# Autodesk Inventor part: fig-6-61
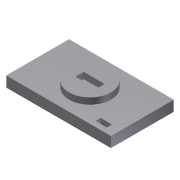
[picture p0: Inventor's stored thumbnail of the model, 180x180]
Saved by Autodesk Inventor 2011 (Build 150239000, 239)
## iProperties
Created: 2007-01
Part Number: fig-6-61
Document SubType Name: Modeling
Designer: Administrator
Density: 1 g/cm^3
Author: Administrator
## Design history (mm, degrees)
sketch "Sketch1"
  geometry: L1 (-50, 30)-(50, 30); L2 (50, 30)-(50, -30); L3 (50, -30)-(-50, -30); L4 (-50, -30)-(-50, 30); 1 further point
  constraints: 8 end point, 2 parallel, 1 horizontal, 1 perpendicular, 1 other
  dimensions: "d0" = 50 distance from line of L4 point (0, 0); "d1" = 100 distance of L1.start L1.end; "d2" = 30 distance from line of L3 point (0, 0); "d3" = 60 distance between parallel lines of L3 L1
extrude "Extrusion1" new body sketch "Sketch1" distance "d4" = 10; taper "d5" = 0 deg
sketch "Sketch2"
  geometry: L1 (10, -4)-(-10, -4); L2 (-10, -4)-(-10, 4); L3 (-10, 4)-(10, 4); L4 (10, 4)-(10, -4); C1 r 20 at (0, 0); 1 further point
  constraints: 8 end point, 2 parallel, 1 centre point, 1 coincident, 1 horizontal, 1 perpendicular, 1 other
  dimensions: "d6" = 40 diameter of C1; "d7" = 4 distance from line of L3 point (0, 0); "d8" = 8 distance between parallel lines of L1 L3; "d9" = 10 distance from line of L2 point (0, 0); "d10" = 20 distance between parallel lines of L4 L2
extrude "Extrusion2" join sketch "Sketch2" distance "d11" = 6; taper "d12" = 0 deg
sketch "Sketch3"
  geometry: L1 (30, -20)-(41, -20); L2 (41, -20)-(41, -25); L3 (41, -25)-(30, -25); L4 (30, -25)-(30, -20)
  constraints: 8 end point, 2 parallel, 1 horizontal, 1 perpendicular
extrude "Extrusion3" cut sketch "Sketch3" stored distance "d13" = 10; taper "d14" = 0 deg
body "Solid1"
